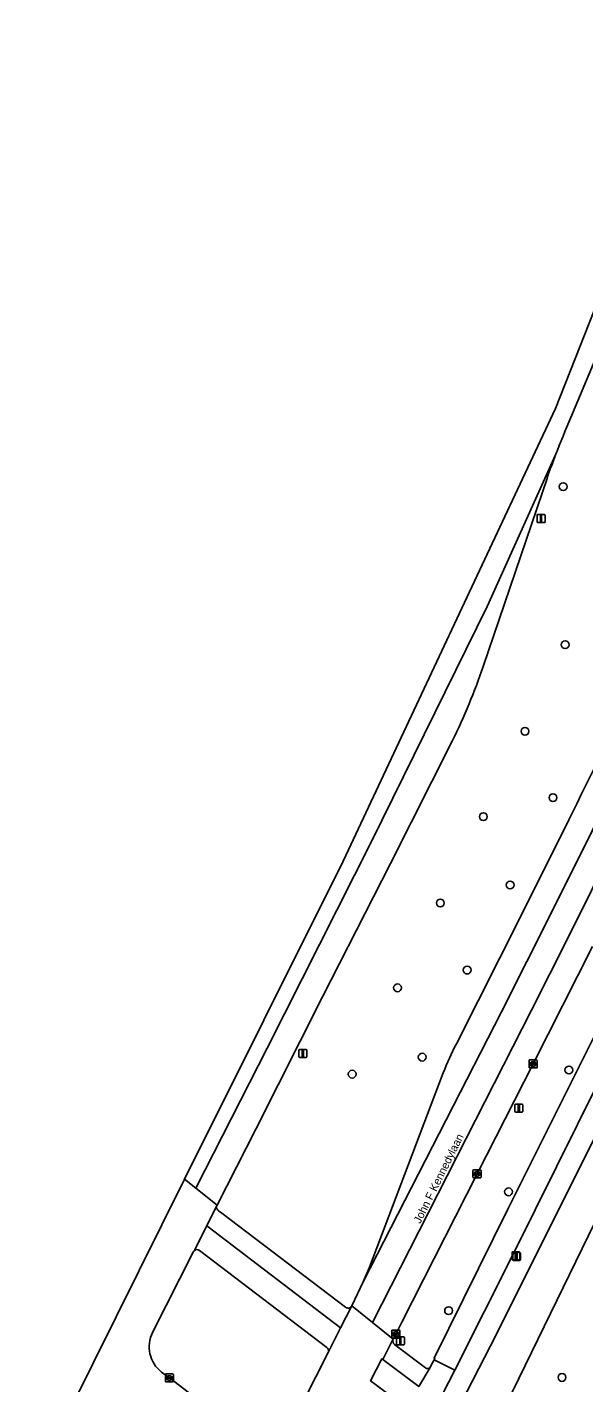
# Model space of a CAD drawing. Extents: x 161477 to 163040, y 383680 to 384871.
# Drawn here: x 161640.1 to 161709.6, y 384580.8 to 384750.3 of the extents above; entities that cross this region are included whole.
import ezdxf

# ---------------------------------------------------------------- set-up
doc = ezdxf.new("R2010")
doc.units = 0
for name, color, linetype in [('IMGEO_Berm_groen', 7, 'Continuous'), ('IMGEO_Boom', 7, 'Continuous'), ('IMGEO_Fietspad_gesloten', 7, 'Continuous'), ('IMGEO_Groenvoorziening', 7, 'Continuous'), ('IMGEO_Hek', 7, 'Continuous'), ('IMGEO_Kolk', 7, 'Continuous'), ('IMGEO_Lichtmast', 7, 'Continuous'), ('IMGEO_Openbare_ruimte_label', 7, 'Continuous'), ('IMGEO_Rijbaan_lokaal_gesloten', 7, 'Continuous'), ('IMGEO_Verkeersbordpaal', 7, 'Continuous'), ('IMGEO_Verkeerseiland_groen', 7, 'Continuous'), ('IMGEO_Voetpad_open', 7, 'Continuous')]:
    doc.layers.add(name, color=color, linetype=linetype)

msp = doc.modelspace()

# ---------------------------------------------------------------- linework, layer by layer
at = {"layer": 'IMGEO_Berm_groen'}
for points in [[(161712.26, 384711.63), (161708.01, 384701.5)], [(161690.43, 384582.79), (161690.53, 384582.97), (161690.92, 384583.73), (161691.02, 384583.89), (161690.92, 384583.94), (161700.14, 384602.58), (161711.46, 384625.22), (161739.38, 384681.88), (161744.96, 384693.15), (161745.02, 384693.26)], [(161705.08, 384694.01), (161697.05, 384670.38)], [(161693.24, 384661.14), (161685.48, 384645.77), (161676.99, 384629.09), (161668.63, 384612.55), (161663.82, 384603.08), (161663.78, 384603.01)], [(161693.71, 384623.23), (161701.81, 384639.27), (161707.8, 384651.29)], [(161710.73, 384635.38), (161703.31, 384620.71), (161696.29, 384606.97), (161686.9, 384588.44), (161686.14, 384586.94), (161685.81, 384586.32), (161685.8, 384586.29), (161685.79, 384586.26)], [(161680.64, 384590.46), (161682.08, 384593.49), (161682.85, 384595.3), (161692.07, 384619.6)], [(161664, 384602.37), (161664.41, 384602.06), (161679.85, 384590.3)], [(161686, 384585.65), (161689.85, 384582.72)]]:
    msp.add_lwpolyline(points, dxfattribs=at)
for centre, radius, start, end in [((161816.25, 384654.88), 117.85, 156.6959, 159.1541), ((161816.62, 384654.67), 118.28, 159.1214, 160.5725), ((160567.26, 385216.55), 1272.93, 333.63656, 335.24715), ((161627.42, 384693.67), 73.42, 333.7034, 341.5102), ((161720.98, 384608.69), 30.9, 151.9359, 159.3239), ((161664.24, 384602.81), 0.498, 156.4603, 241.3798), ((161680.18, 384590.73), 0.537, 232.1886, 329.9034), ((161686.31, 384586.1), 0.547, 162.2517, 235.2309), ((161690.09, 384583.11), 0.465, 238.2604, 316.594)]:
    msp.add_arc(centre, radius, start, end, dxfattribs=at)
at = {"layer": 'IMGEO_Boom'}
for centre in [(161707.06, 384692.86), (161707.31, 384673.11), (161702.29, 384662.28), (161705.78, 384653.99), (161697.08, 384651.62), (161700.43, 384643.07), (161691.7, 384640.83), (161695.06, 384632.44), (161686.36, 384630.23), (161689.44, 384621.56), (161707.77, 384619.95), (161680.69, 384619.43), (161700.23, 384604.73), (161692.74, 384589.88), (161706.91, 384581.53)]:
    msp.add_circle(centre, 0.489, dxfattribs=at)
at = {"layer": 'IMGEO_Fietspad_gesloten'}
for points in [[(161799.43, 384807.73), (161754.43, 384712.97), (161751.19, 384706.16), (161749.45, 384702.51), (161746.32, 384695.97), (161745.02, 384693.26), (161744.96, 384693.15), (161739.38, 384681.88), (161711.46, 384625.22), (161700.14, 384602.58), (161690.92, 384583.94), (161691.02, 384583.89), (161690.92, 384583.73), (161693.51, 384582.44), (161700.89, 384597.12), (161714.18, 384623.88), (161742.25, 384680.7), (161742.52, 384681.24), (161744.07, 384684.42), (161747.38, 384691.21), (161750.62, 384697.89), (161803.16, 384808.47)], [(161662.51, 384600.49), (161660.94, 384597.36)], [(161677.71, 384584.65), (161679.23, 384587.73), (161662.51, 384600.49)], [(161661.61, 384597.4), (161677.54, 384585.27)], [(161686.21, 384568.22), (161693.51, 384582.44), (161690.92, 384583.73), (161690.53, 384582.97), (161690.43, 384582.79), (161689.01, 384580.38), (161684.53, 384583.75), (161684.38, 384583.85), (161682.96, 384581.11), (161683.59, 384580.66), (161687.33, 384577.84)]]:
    msp.add_lwpolyline(points, dxfattribs=at)
for centre, radius, start, end in [((161661.3, 384596.97), 0.532, 54.5656, 132.9378), ((161677.25, 384584.86), 0.501, 334.7308, 55.1891)]:
    msp.add_arc(centre, radius, start, end, dxfattribs=at)
at = {"layer": 'IMGEO_Groenvoorziening'}
msp.add_lwpolyline([(161949.97, 384804.11), (161836.57, 384803.92), (161810.11, 384804.01), (161782.92, 384748.04), (161733.01, 384645.95), (161725.31, 384630.21), (161692.77, 384563.44)], dxfattribs=at)
msp.add_lwpolyline([(161725.31, 384630.21), (161721.18, 384632.05), (161717.58, 384624.7), (161697.99, 384585.48), (161691.41, 384572.68), (161689.66, 384569.1), (161693.19, 384567.3), (161693, 384565.52), (161692.77, 384563.44)], close=True, dxfattribs=at)
at = {"layer": 'IMGEO_Hek'}
msp.add_lwpolyline([(161725.31, 384630.21), (161694.36, 384566.71)], dxfattribs=at)
at = {"layer": 'IMGEO_Kolk'}
for p, q in [((161702.81, 384620.29), (161702.81, 384621.14)), ((161702.88, 384621.21), (161703.73, 384621.21)), ((161703.73, 384620.21), (161702.88, 384620.21)), ((161703.07, 384620.71), (161703.07, 384620.72)), ((161703.11, 384620.76), (161703.51, 384620.76)), ((161703.5, 384620.67), (161703.11, 384620.67)), ((161703.32, 384620.43), (161703.29, 384620.43)), ((161703.3, 384620.99), (161703.32, 384620.99)), ((161703.55, 384620.72), (161703.55, 384620.71)), ((161703.81, 384621.14), (161703.81, 384620.29)), ((161695.78, 384606.54), (161695.78, 384607.4)), ((161695.86, 384607.47), (161696.71, 384607.47)), ((161696.04, 384606.96), (161696.04, 384606.98)), ((161696.48, 384606.93), (161696.08, 384606.93)), ((161696.09, 384607.01), (161696.48, 384607.01)), ((161696.27, 384607.25), (161696.3, 384607.25)), ((161696.29, 384606.69), (161696.27, 384606.69)), ((161696.53, 384606.98), (161696.53, 384606.96)), ((161696.79, 384607.4), (161696.79, 384606.54)), ((161696.71, 384606.47), (161695.86, 384606.47)), ((161685.64, 384586.52), (161685.64, 384587.37)), ((161685.71, 384587.44), (161686.57, 384587.44)), ((161686.57, 384586.44), (161685.71, 384586.44)), ((161685.9, 384586.94), (161685.9, 384586.95)), ((161685.94, 384586.99), (161686.34, 384586.99)), ((161686.33, 384586.9), (161685.94, 384586.9)), ((161686.15, 384586.66), (161686.12, 384586.66)), ((161686.13, 384587.22), (161686.15, 384587.22)), ((161686.38, 384586.95), (161686.38, 384586.94)), ((161686.64, 384587.37), (161686.64, 384586.52)), ((161657.34, 384581.03), (161657.34, 384581.89)), ((161657.41, 384581.96), (161658.27, 384581.96)), ((161657.6, 384581.45), (161657.6, 384581.47)), ((161657.64, 384581.5), (161658.04, 384581.5)), ((161658.04, 384581.42), (161657.64, 384581.42)), ((161657.85, 384581.18), (161657.82, 384581.18)), ((161657.83, 384581.74), (161657.85, 384581.74)), ((161658.08, 384581.47), (161658.08, 384581.45)), ((161658.34, 384581.89), (161658.34, 384581.03)), ((161658.27, 384580.96), (161657.41, 384580.96))]:
    msp.add_line(p, q, dxfattribs=at)
for points in [[(161702.81, 384620.29), (161702.81, 384621.14)], [(161702.88, 384621.21), (161703.73, 384621.21)], [(161703.73, 384620.21), (161702.88, 384620.21)], [(161703.81, 384621.14), (161703.81, 384620.29)], [(161695.78, 384606.54), (161695.78, 384607.4)], [(161695.86, 384607.47), (161696.71, 384607.47)], [(161696.79, 384607.4), (161696.79, 384606.54)], [(161696.71, 384606.47), (161695.86, 384606.47)], [(161685.64, 384586.52), (161685.64, 384587.37)], [(161685.71, 384587.44), (161686.57, 384587.44)], [(161686.57, 384586.44), (161685.71, 384586.44)], [(161686.64, 384587.37), (161686.64, 384586.52)], [(161657.34, 384581.03), (161657.34, 384581.89)], [(161657.41, 384581.96), (161658.27, 384581.96)], [(161658.34, 384581.89), (161658.34, 384581.03)], [(161658.27, 384580.96), (161657.41, 384580.96)]]:
    msp.add_lwpolyline(points, dxfattribs=at)
for centre, radius, start, end in [((161702.88, 384621.14), 0.0765, 91.552, 178.448), ((161702.88, 384621.14), 0.0765, 91.552, 178.448), ((161702.88, 384620.29), 0.0765, 181.552, 268.448), ((161702.88, 384620.29), 0.0765, 181.552, 268.448), ((161703.11, 384620.72), 0.0403, 85.8775, 175.7526), ((161703.1, 384620.71), 0.0366, 178.938, 274.7102), ((161703.51, 384620.71), 0.043, 264.8664, 352.4533), ((161703.51, 384620.72), 0.0386, 1.7309, 96.639), ((161703.73, 384621.14), 0.0765, 1.552, 88.448), ((161703.73, 384621.14), 0.0765, 1.552, 88.448), ((161703.73, 384620.29), 0.0765, 271.552, 358.448), ((161703.73, 384620.29), 0.0765, 271.552, 358.448), ((161695.86, 384607.39), 0.0765, 91.552, 178.448), ((161695.86, 384607.39), 0.0765, 91.552, 178.448), ((161696.08, 384606.97), 0.0403, 85.8775, 175.7526), ((161696.08, 384606.96), 0.0366, 178.938, 274.7102), ((161696.49, 384606.97), 0.0386, 1.7309, 96.639), ((161696.48, 384606.97), 0.043, 264.8664, 352.4533), ((161696.71, 384607.39), 0.0765, 1.552, 88.448), ((161696.71, 384607.39), 0.0765, 1.552, 88.448), ((161695.86, 384606.54), 0.0765, 181.552, 268.448), ((161695.86, 384606.54), 0.0765, 181.552, 268.448), ((161696.71, 384606.54), 0.0765, 271.552, 358.448), ((161696.71, 384606.54), 0.0765, 271.552, 358.448), ((161685.71, 384587.37), 0.0765, 91.552, 178.448), ((161685.71, 384587.37), 0.0765, 91.552, 178.448), ((161685.71, 384586.52), 0.0765, 181.552, 268.448), ((161685.71, 384586.52), 0.0765, 181.552, 268.448), ((161685.94, 384586.95), 0.0403, 85.8775, 175.7526), ((161685.93, 384586.94), 0.0366, 178.938, 274.7102), ((161686.34, 384586.94), 0.043, 264.8664, 352.4533), ((161686.34, 384586.95), 0.0386, 1.7309, 96.639), ((161686.56, 384587.37), 0.0765, 1.552, 88.448), ((161686.56, 384587.37), 0.0765, 1.552, 88.448), ((161686.56, 384586.52), 0.0765, 271.552, 358.448), ((161686.56, 384586.52), 0.0765, 271.552, 358.448), ((161657.42, 384581.89), 0.0765, 91.552, 178.448), ((161657.42, 384581.89), 0.0765, 91.552, 178.448), ((161657.64, 384581.46), 0.0403, 85.8775, 175.7526), ((161657.63, 384581.45), 0.0366, 178.938, 274.7102), ((161658.04, 384581.47), 0.0386, 1.7309, 96.639), ((161658.04, 384581.46), 0.043, 264.8664, 352.4533), ((161658.26, 384581.89), 0.0765, 1.552, 88.448), ((161658.26, 384581.89), 0.0765, 1.552, 88.448), ((161657.42, 384581.04), 0.0765, 181.552, 268.448), ((161657.42, 384581.04), 0.0765, 181.552, 268.448), ((161658.26, 384581.04), 0.0765, 271.552, 358.448), ((161658.26, 384581.04), 0.0765, 271.552, 358.448)]:
    msp.add_arc(centre, radius, start, end, dxfattribs=at)
for centre, major_axis, ratio, start_param, end_param in [((161703.29, 384620.71), (-0.387, 0.002), 0.722429, 4.712389, 7.853982), ((161703.32, 384620.71), (-0.39, 0.002), 0.717154, 1.570796, 4.712389), ((161696.27, 384606.97), (-0.387, 0.002), 0.722429, 4.712389, 7.853982), ((161696.3, 384606.97), (-0.39, 0.002), 0.717154, 1.570796, 4.712389), ((161686.13, 384586.94), (-0.387, 0.002), 0.722429, 4.712389, 7.853982), ((161686.15, 384586.94), (-0.39, 0.002), 0.717154, 1.570796, 4.712389), ((161657.83, 384581.46), (-0.387, 0.002), 0.722429, 4.712389, 7.853982), ((161657.85, 384581.46), (-0.39, 0.002), 0.717154, 1.570796, 4.712389)]:
    msp.add_ellipse(centre, major_axis=major_axis, ratio=ratio, start_param=start_param, end_param=end_param, dxfattribs=at)
at = {"layer": 'IMGEO_Lichtmast'}
for p, q in [((161701.02, 384614.78), (161701.02, 384615.58)), ((161701.02, 384615.58), (161701.02, 384614.78)), ((161701.12, 384615.68), (161701.91, 384615.68)), ((161701.91, 384615.68), (161701.12, 384615.68)), ((161702.01, 384615.58), (161702.01, 384614.78)), ((161702.01, 384614.78), (161702.01, 384615.58)), ((161701.91, 384614.68), (161701.12, 384614.68)), ((161701.12, 384614.68), (161701.91, 384614.68)), ((161700.67, 384596.32), (161700.67, 384597.12)), ((161700.67, 384597.12), (161700.67, 384596.32)), ((161700.75, 384596.24), (161700.75, 384597.04)), ((161700.75, 384597.04), (161700.75, 384596.24)), ((161700.77, 384597.22), (161701.55, 384597.22)), ((161701.55, 384597.22), (161700.77, 384597.22)), ((161700.85, 384597.14), (161701.63, 384597.14)), ((161701.63, 384597.14), (161700.85, 384597.14)), ((161701.65, 384597.12), (161701.65, 384596.32)), ((161701.65, 384596.32), (161701.65, 384597.12)), ((161701.73, 384597.04), (161701.73, 384596.24)), ((161701.73, 384596.24), (161701.73, 384597.04)), ((161701.55, 384596.22), (161700.77, 384596.22)), ((161700.77, 384596.22), (161701.55, 384596.22)), ((161701.63, 384596.14), (161700.85, 384596.14)), ((161700.85, 384596.14), (161701.63, 384596.14)), ((161686.22, 384585.7), (161686.22, 384586.5)), ((161686.22, 384586.5), (161686.22, 384585.7)), ((161686.32, 384586.6), (161687.11, 384586.6)), ((161687.11, 384586.6), (161686.32, 384586.6)), ((161687.21, 384586.5), (161687.21, 384585.7)), ((161687.21, 384585.7), (161687.21, 384586.5)), ((161687.11, 384585.6), (161686.32, 384585.6)), ((161686.32, 384585.6), (161687.11, 384585.6))]:
    msp.add_line(p, q, dxfattribs=at)
for points in [[(161701.44, 384615.55), (161701.59, 384615.55), (161701.59, 384614.8), (161701.44, 384614.8), (161701.44, 384615.55)], [(161701.08, 384597.09), (161701.24, 384597.09), (161701.24, 384596.34), (161701.08, 384596.34), (161701.08, 384597.09)], [(161701.16, 384597.01), (161701.32, 384597.01), (161701.32, 384596.26), (161701.16, 384596.26), (161701.16, 384597.01)], [(161686.64, 384586.48), (161686.79, 384586.48), (161686.79, 384585.73), (161686.64, 384585.73), (161686.64, 384586.48)]]:
    msp.add_lwpolyline(points, dxfattribs=at)
for centre, start, end in [((161701.12, 384615.58), 90, 180), ((161701.12, 384615.58), 90, 180), ((161701.91, 384615.58), 0, 90), ((161701.91, 384615.58), 360, 90), ((161701.12, 384614.78), 180, 270), ((161701.12, 384614.78), 180, 270), ((161701.91, 384614.78), 270, 0), ((161701.91, 384614.78), 270, 0), ((161700.77, 384597.12), 90, 180), ((161700.77, 384597.12), 90, 180), ((161700.85, 384597.04), 90, 180), ((161700.85, 384597.04), 90, 180), ((161701.55, 384597.12), 0, 90), ((161701.55, 384597.12), 360, 90), ((161701.63, 384597.04), 0, 90), ((161701.63, 384597.04), 360, 90), ((161700.77, 384596.32), 180, 270), ((161700.77, 384596.32), 180, 270), ((161700.85, 384596.24), 180, 270), ((161700.85, 384596.24), 180, 270), ((161701.55, 384596.32), 270, 0), ((161701.55, 384596.32), 270, 0), ((161701.63, 384596.24), 270, 0), ((161701.63, 384596.24), 270, 0), ((161686.32, 384586.5), 90, 180), ((161686.32, 384586.5), 90, 180), ((161687.11, 384586.5), 0, 90), ((161687.11, 384586.5), 360, 90), ((161686.32, 384585.7), 180, 270), ((161686.32, 384585.7), 180, 270), ((161687.11, 384585.7), 270, 0), ((161687.11, 384585.7), 270, 0)]:
    msp.add_arc(centre, 0.1, start, end, dxfattribs=at)
at = {"layer": 'IMGEO_Rijbaan_lokaal_gesloten'}
for points in [[(161718.67, 384728.11), (161721.59, 384735.89), (161724.85, 384744.97), (161729.42, 384758.16), (161733.61, 384770.36), (161738.08, 384783.7), (161740.39, 384791.04), (161746.3, 384811.92), (161747.33, 384815.87), (161745.21, 384816.14), (161740.76, 384796.63), (161726.15, 384753.41), (161706.08, 384702.62), (161679.56, 384646.07), (161659.74, 384606.29)], [(161760.83, 384754.35), (161755.82, 384742.03), (161748.31, 384724), (161743.88, 384713.76), (161743.88, 384713.75), (161739.05, 384702.74), (161734.13, 384691.77), (161729.11, 384680.85), (161724.05, 384669.99), (161718.87, 384659.18), (161713.6, 384648.41), (161713.6, 384648.41), (161707.6, 384636.36), (161703.1, 384627.45), (161683.23, 384588.39), (161685.81, 384586.32), (161686.14, 384586.94), (161686.9, 384588.44), (161696.29, 384606.97), (161703.31, 384620.71), (161710.73, 384635.38)], [(161692.07, 384619.6), (161682.85, 384595.3), (161682.08, 384593.49), (161700.21, 384628.91), (161700.36, 384629.22), (161704.7, 384637.82), (161710.7, 384649.85), (161710.7, 384649.85), (161715.96, 384660.59), (161718.67, 384666.24), (161721.12, 384671.37), (161726.18, 384682.21), (161731.18, 384693.11), (161736.09, 384704.05), (161740.91, 384715.04)], [(161708.01, 384701.5), (161712.26, 384711.63)], [(161659.74, 384606.29), (161661.16, 384605.17), (161670.06, 384622.7), (161683.15, 384648.61), (161697.58, 384677.87), (161706.11, 384696.82)], [(161706.11, 384696.82), (161697.58, 384677.87), (161683.15, 384648.61), (161670.06, 384622.7), (161661.16, 384605.17), (161663.82, 384603.08), (161668.63, 384612.55), (161676.99, 384629.09), (161685.48, 384645.77), (161693.24, 384661.14)], [(161697.05, 384670.38), (161705.08, 384694.01)], [(161707.8, 384651.29), (161701.81, 384639.27), (161693.71, 384623.23)], [(161710.7, 384649.85), (161704.7, 384637.82), (161700.36, 384629.22), (161700.21, 384628.91), (161682.08, 384593.49), (161680.64, 384590.46), (161683.23, 384588.39), (161703.1, 384627.45), (161707.6, 384636.36), (161713.6, 384648.41)], [(161660.94, 384597.36), (161662.51, 384600.49), (161663.78, 384603.01), (161663.82, 384603.08), (161661.16, 384605.17), (161659.74, 384606.29), (161648.35, 384583.41), (161640.07, 384566.79)], [(161655.73, 384587.15), (161660.82, 384597.19)], [(161683.59, 384580.66), (161682.96, 384581.11), (161684.38, 384583.85), (161684.53, 384583.75), (161685.79, 384586.26), (161685.8, 384586.29), (161685.81, 384586.32), (161683.23, 384588.39), (161680.64, 384590.46), (161679.23, 384587.73), (161677.71, 384584.65), (161673.11, 384575.6)], [(161667.15, 384574.36), (161666.17, 384575.12), (161657.84, 384581.46), (161656.86, 384582.2)]]:
    msp.add_lwpolyline(points, dxfattribs=at)
for centre, radius, start, end in [((161816.25, 384654.88), 117.85, 156.6959, 159.1541), ((161816.62, 384654.67), 118.28, 159.1214, 160.5725), ((160567.26, 385216.55), 1272.93, 333.63656, 335.24715), ((161627.42, 384693.67), 73.42, 333.7034, 341.5102), ((161720.98, 384608.69), 30.9, 151.9359, 159.3239), ((161661.32, 384596.96), 0.548, 133.6334, 155.0955), ((161659.35, 384585.38), 4.03, 153.8461, 231.9114)]:
    msp.add_arc(centre, radius, start, end, dxfattribs=at)
at = {"layer": 'IMGEO_Verkeersbordpaal'}
for p, q in [((161703.8, 384688.47), (161703.8, 384689.27)), ((161703.8, 384689.27), (161703.8, 384688.47)), ((161703.9, 384689.37), (161704.69, 384689.37)), ((161704.69, 384689.37), (161703.9, 384689.37)), ((161704.69, 384688.37), (161703.9, 384688.37)), ((161703.9, 384688.37), (161704.69, 384688.37)), ((161704.79, 384689.27), (161704.79, 384688.47)), ((161704.79, 384688.47), (161704.79, 384689.27)), ((161674.04, 384621.61), (161674.04, 384622.41)), ((161674.04, 384622.41), (161674.04, 384621.61)), ((161674.14, 384622.51), (161674.93, 384622.51)), ((161674.93, 384622.51), (161674.14, 384622.51)), ((161675.03, 384622.41), (161675.03, 384621.61)), ((161675.03, 384621.61), (161675.03, 384622.41)), ((161674.93, 384621.51), (161674.14, 384621.51)), ((161674.14, 384621.51), (161674.93, 384621.51))]:
    msp.add_line(p, q, dxfattribs=at)
for points in [[(161704.22, 384689.24), (161704.37, 384689.24), (161704.37, 384688.49), (161704.22, 384688.49), (161704.22, 384689.24)], [(161674.46, 384622.39), (161674.61, 384622.39), (161674.61, 384621.64), (161674.46, 384621.64), (161674.46, 384622.39)]]:
    msp.add_lwpolyline(points, dxfattribs=at)
for centre, start, end in [((161703.9, 384689.27), 90, 180), ((161703.9, 384689.27), 90, 180), ((161703.9, 384688.47), 180, 270), ((161703.9, 384688.47), 180, 270), ((161704.69, 384689.27), 0, 90), ((161704.69, 384689.27), 360, 90), ((161704.69, 384688.47), 270, 0), ((161704.69, 384688.47), 270, 0), ((161674.14, 384622.41), 90, 180), ((161674.14, 384622.41), 90, 180), ((161674.93, 384622.41), 0, 90), ((161674.93, 384622.41), 360, 90), ((161674.14, 384621.61), 180, 270), ((161674.14, 384621.61), 180, 270), ((161674.93, 384621.61), 270, 0), ((161674.93, 384621.61), 270, 0)]:
    msp.add_arc(centre, 0.1, start, end, dxfattribs=at)
at = {"layer": 'IMGEO_Verkeerseiland_groen'}
for points in [[(161660.82, 384597.19), (161655.73, 384587.15)], [(161677.54, 384585.27), (161661.61, 384597.4)], [(161673.11, 384575.6), (161677.71, 384584.65)], [(161656.86, 384582.2), (161657.84, 384581.46), (161666.17, 384575.12), (161667.15, 384574.36)]]:
    msp.add_lwpolyline(points, dxfattribs=at)
for centre, radius, start, end in [((161661.32, 384596.96), 0.548, 133.6334, 155.0955), ((161661.3, 384596.97), 0.532, 54.5656, 132.9378), ((161659.35, 384585.38), 4.03, 153.8461, 231.9114), ((161677.25, 384584.86), 0.501, 334.7308, 55.1891)]:
    msp.add_arc(centre, radius, start, end, dxfattribs=at)
at = {"layer": 'IMGEO_Voetpad_open'}
for points in [[(161803.91, 384809.96), (161803.16, 384808.47), (161750.62, 384697.89), (161747.38, 384691.21), (161744.07, 384684.42), (161742.52, 384681.24), (161742.25, 384680.7), (161714.18, 384623.88), (161700.89, 384597.12), (161693.51, 384582.44), (161686.21, 384568.22)], [(161687.08, 384564.18), (161688.86, 384567.55), (161690.88, 384566.53), (161693, 384565.52), (161693.19, 384567.3), (161689.66, 384569.1), (161691.41, 384572.68), (161697.99, 384585.48), (161717.58, 384624.7), (161721.18, 384632.05), (161728.71, 384647.38), (161729.22, 384648.41), (161741.12, 384672.51), (161751.68, 384693.98)], [(161663.78, 384603.01), (161662.51, 384600.49), (161679.23, 384587.73), (161680.64, 384590.46)], [(161664.41, 384602.06), (161664, 384602.37)], [(161679.85, 384590.3), (161664.41, 384602.06)], [(161685.79, 384586.26), (161684.53, 384583.75), (161689.01, 384580.38), (161690.43, 384582.79)], [(161689.85, 384582.72), (161686, 384585.65)]]:
    msp.add_lwpolyline(points, dxfattribs=at)
for centre, radius, start, end in [((161664.24, 384602.81), 0.498, 156.4603, 241.3798), ((161680.18, 384590.73), 0.537, 232.1886, 329.9034), ((161686.31, 384586.1), 0.547, 162.2517, 235.2309), ((161690.09, 384583.11), 0.465, 238.2604, 316.594)]:
    msp.add_arc(centre, radius, start, end, dxfattribs=at)

# ---------------------------------------------------------------- texts
at = {"layer": 'IMGEO_Openbare_ruimte_label'}
msp.add_text('John F Kennedylaan', height=1, rotation=63.5631, dxfattribs=at).set_placement((161689.2, 384600.68))

doc.saveas('drawing.dxf')
